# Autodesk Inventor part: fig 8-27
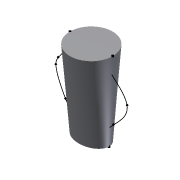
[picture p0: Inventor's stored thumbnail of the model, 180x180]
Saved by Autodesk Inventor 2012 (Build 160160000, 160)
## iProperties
Shininess: 64.0
Length Units: 11269
Angle Units: 11279
Time Units: 11290
Mass Units: 11283
Length Display Precision: 3
Angle Display Precision: 2
Compacted: True
Part Number: fig 8-27
Document SubType Name: Modeling
Created: 2002-12
Designer: deepak
Density: 1 g/cm^3
Material: Default
Density: 0.0
Volumn: 0.0
Area: 0.0
PropertySet Name: Model Information
Control State: 0
Master: False
Checked Out: False
Author: deepak
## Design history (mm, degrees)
sketch "Sketch1"
  geometry: 2 further points; 1 other entity
  constraints: 1 coincident, 3 other
workplane "Work Plane1"
workplane "Work Plane2"
sketch "Sketch3"
  geometry: C1 r 60 at (0, 0); 1 further point
  constraints: 1 centre point, 1 coincident, 1 other
sketch "Sketch4"
  geometry: 8 further points
  constraints: 8 other
sketch "Sketch5"
  geometry: 6 further points
  constraints: 6 other
sketch "Sketch6"
  geometry: 6 further points
  constraints: 6 other
  dimensions: "d20" = 35 distance of point (0, 0) point (-35, 0); "d21" = 0 vertical distance of point (0, 0) point (-35, 0); "d22" = 225 vertical distance of point (0, 0) point (-60, 225); "d23" = 60 horizontal distance of point (0, 0) point (-60, 225); "d24" = 100 horizontal distance of point (0, 0) point (-100, 125); "d25" = 125 vertical distance of point (0, 0) point (-100, 125)
loft "Loft4" dims "d50" = 0, "d51" = 90 deg, "d52" = 0, "d53" = 90 deg
body "Solid1"
other parameters: "d5" = 125
